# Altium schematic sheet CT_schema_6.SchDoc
size 422 x 246 mm
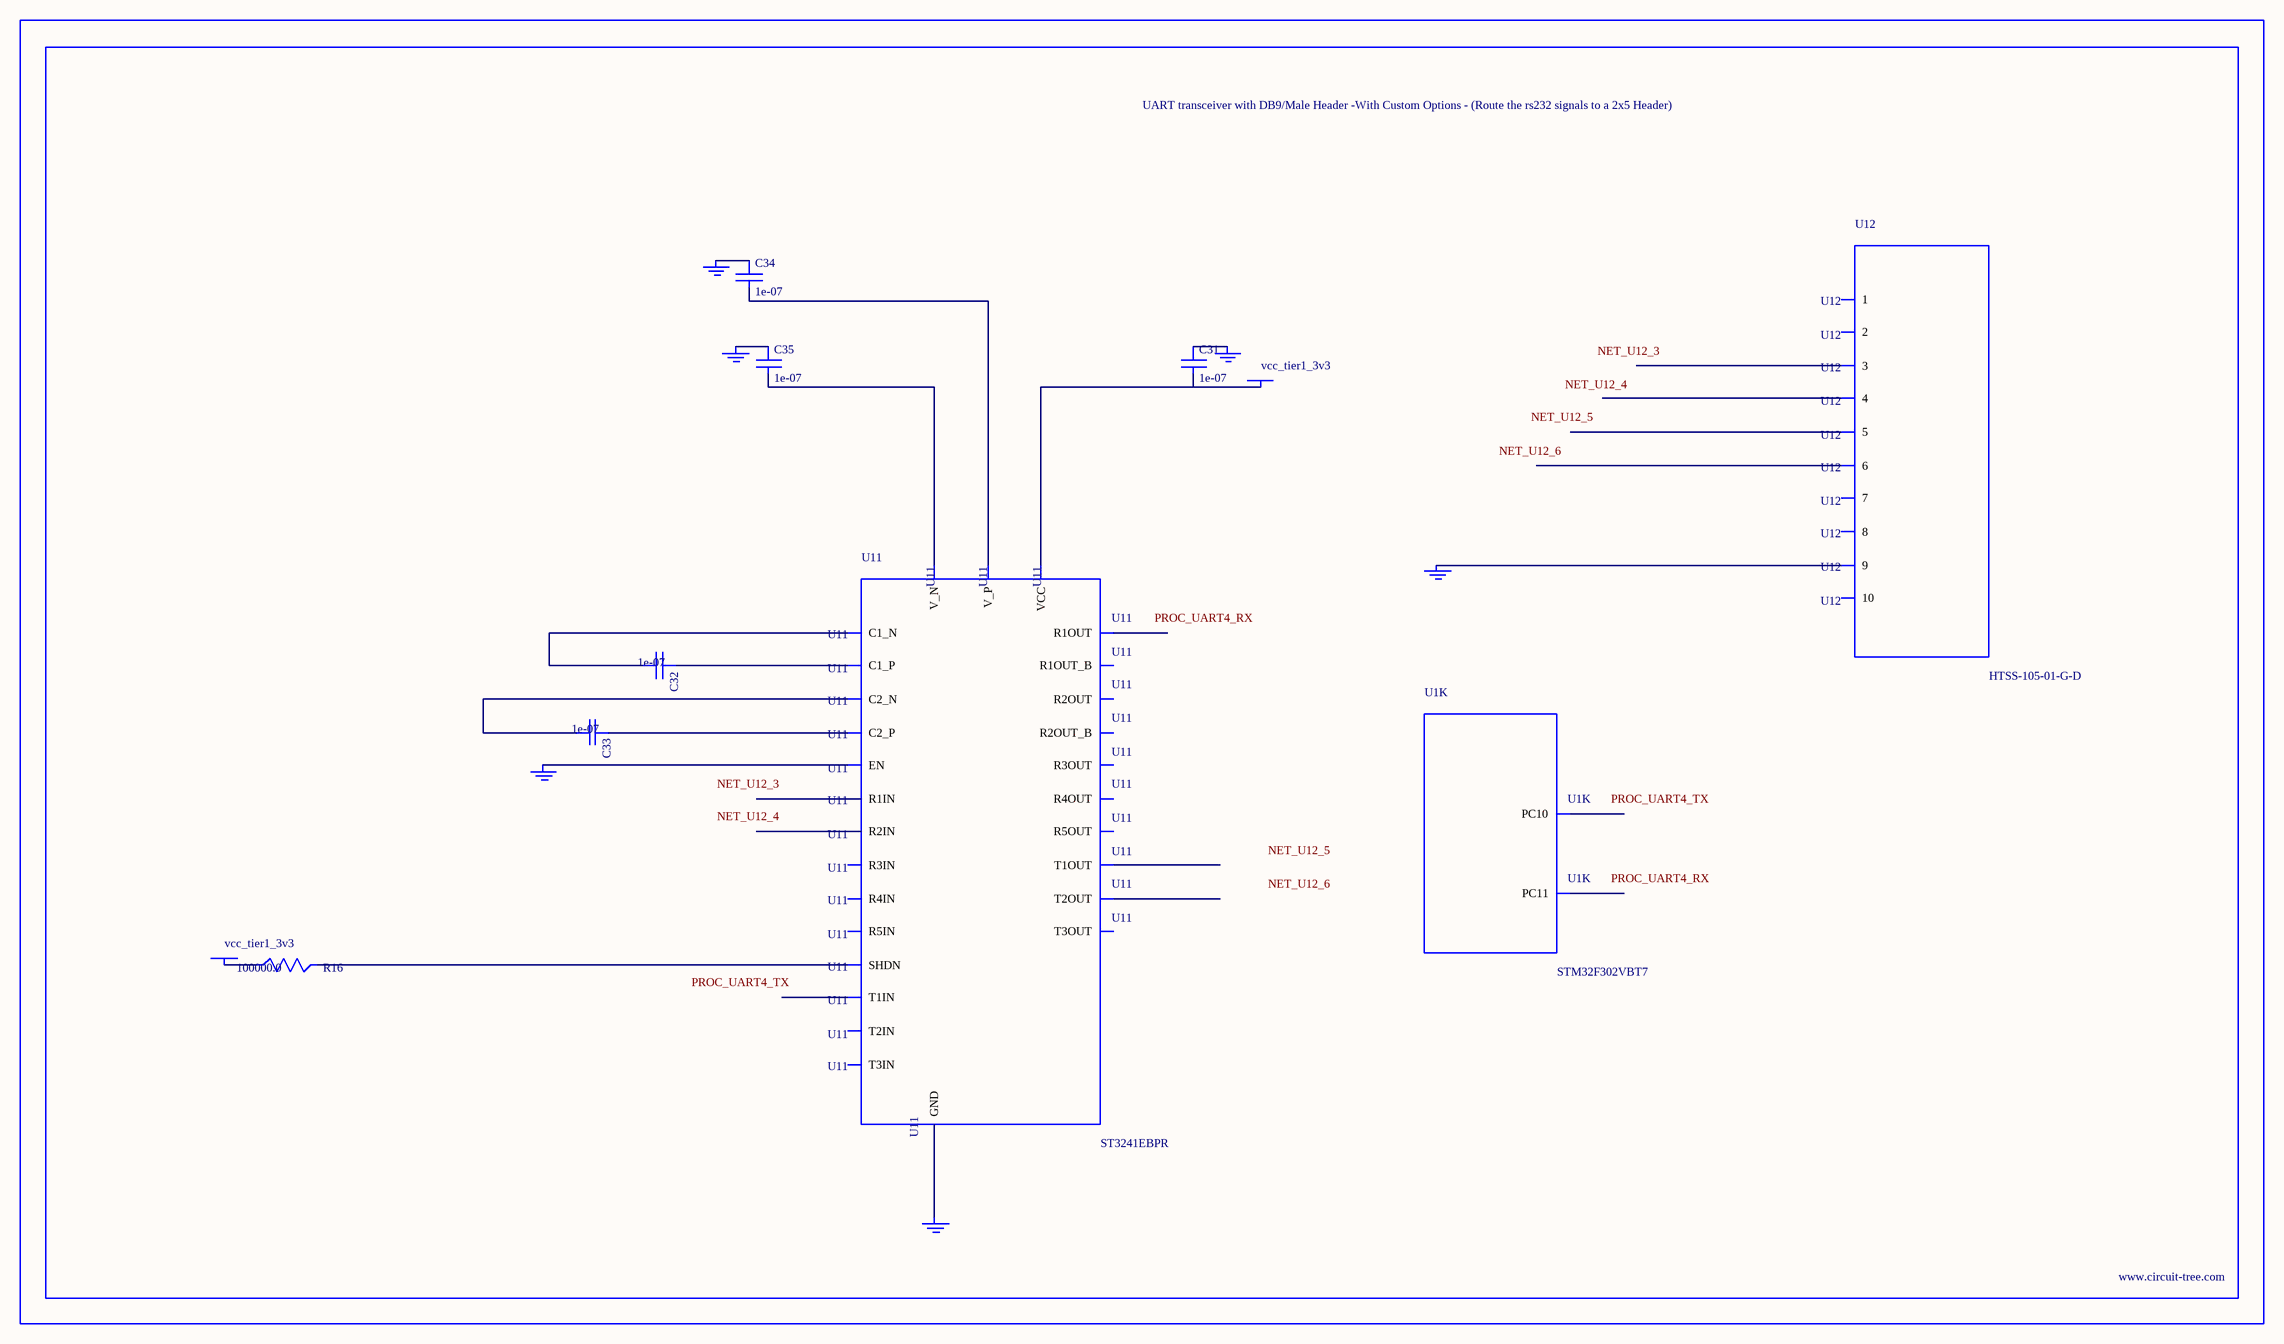
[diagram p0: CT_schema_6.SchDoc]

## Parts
BORDER5  (no value)
C31  1e-07  [C0402]
C32  1e-07  [C0402]
C33  1e-07  [C0402]
C34  1e-07  [C0402]
C35  1e-07  [C0402]
GND_INSTANCE_5_0  (no value)
GND_INSTANCE_5_1  (no value)
GND_INSTANCE_5_2  (no value)
GND_INSTANCE_5_3  (no value)
GND_INSTANCE_5_4  (no value)
GND_INSTANCE_5_5  (no value)
POWER_INSTANCE_5_0  vcc_tier1_3v3
POWER_INSTANCE_5_1  vcc_tier1_3v3
R16  100000.0  [R0603]
U1  STM32F302VBT7  [LQFP100]  (part K of 11)
U11  ST3241EBPR  [SSOP-28]
U12  HTSS-105-01-G-D  [HTSS-105-01-G-D]

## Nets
NetC31_1: C31.1 GND_INSTANCE_5_2.0(GND)
NetC31_2: C31.2 POWER_INSTANCE_5_1.0(PWR) U11.26(VCC)
NetC32_1: C32.1 U11.28(C1_P)
NetC32_2: C32.2 U11.24(C1_N)
NetC33_1: C33.1 U11.1(C2_P)
NetC33_2: C33.2 U11.2(C2_N)
NetC34_1: C34.1 GND_INSTANCE_5_3.0(GND)
NetC34_2: C34.2 U11.27(V_P)
NetC35_1: C35.1 GND_INSTANCE_5_0.0(GND)
NetC35_2: C35.2 U11.3(V_N)
NetGND_INSTANCE_5_1_0: GND_INSTANCE_5_1.0(GND) U11.23(EN)
NetGND_INSTANCE_5_4_0: GND_INSTANCE_5_4.0(GND) U11.25(GND)
NetGND_INSTANCE_5_5_0: GND_INSTANCE_5_5.0(GND) U12.9
NetPOWER_INSTANCE_5_0_0: POWER_INSTANCE_5_0.0(PWR) R16.1
NetR16_2: R16.2 U11.22(SHDN)

Not connected (* = marked no-connect by the designer): U1 78(PC10) 79(PC11); U11 4(R1IN) 5(R2IN) 6(R3IN) 7(R4IN) 8(R5IN) 9(T1OUT) 10(T2OUT) 11(T3OUT) 12(T3IN) 13(T2IN) 14(T1IN) 15(R5OUT) 16(R4OUT) 17(R3OUT) 18(R2OUT) 19(R1OUT) 20(R2OUT_B) 21(R1OUT_B); U12 1 2 3 4 5 6 7 8 10

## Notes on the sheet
- Labels drawn without touching a wire or pin: NET_U12_3, NET_U12_4, NET_U12_5, NET_U12_6, PROC_UART4_RX, PROC_UART4_TX

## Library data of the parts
BORDER5 = BORDER_PAGE5
C31-C35 = C0402C104K3RACTU
GND_INSTANCE_5_0-GND_INSTANCE_5_5 = GND
POWER_INSTANCE_5_0 POWER_INSTANCE_5_1 = PWR
R16 = RC0603JR-07100KL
